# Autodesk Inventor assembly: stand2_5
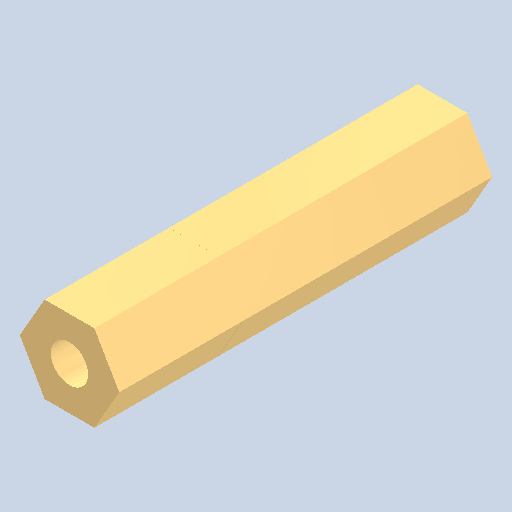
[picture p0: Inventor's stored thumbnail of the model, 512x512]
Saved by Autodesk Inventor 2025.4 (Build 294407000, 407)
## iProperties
Created: 2026-09
Part Number: stand2_5
Document SubType Name: Assembly
Designer: AdminForWorker
Title: stanofff v1
Author: AdminForWorker
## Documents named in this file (3)
- c:\worker\convert-fusion-r05-cosv3\tmp\job-1\19\temp\files\ca3d996b-dda0-445d-8bee-12a194174ca8\stanofff v1_1.iam
- c:\worker\convert-fusion-r05-cosv3\tmp\job-1\19\temp\files\ca3d996b-dda0-445d-8bee-12a194174ca8\M3-10 v1 (2).ipt
- c:\worker\convert-fusion-r05-cosv3\tmp\job-1\19\temp\files\ca3d996b-dda0-445d-8bee-12a194174ca8\M3-20 v1.ipt
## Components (2 placed, 2 different names)
1. M3-10 v1 (2):1
2. M3-20 v1:1
